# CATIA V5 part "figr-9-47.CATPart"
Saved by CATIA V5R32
Part number: Part1
Bounding box of the stored display mesh (mm): x -229.955 to 192.37, y -118.044 to 79.893, z 0 to 72.429
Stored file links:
  D:\PROJECTS\Project 2022\CATIA V5 6R 2022\Resources\Part Files\c09_catia_v5_6r2022_prt\c09_catia_v5_6r2022_prt\figr-9-47.CATPart
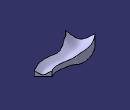
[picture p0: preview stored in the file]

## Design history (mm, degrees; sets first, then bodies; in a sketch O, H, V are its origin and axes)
Body1 (main body)
  Plane1: type Offset, RefPlane yz-plane, Offset 100
  Plane2: type Offset, RefPlane yz-plane, Offset 100, reversed
  Sketch1 on Plane1, origin (100, 0, 0), H (0, 1, 0), V (0, 0, 1)
    point P1 (0, 15.965)
    hyperbola C1
    point P2 (0, 3.0416)
    line L1 (54.8261, 44.8858) -> (54.8261, 0)
    point P5 (54.8261, 0)
    line L2 (-54.8261, 44.8858) -> (-54.8261, 0)
    point P6 (-54.8261, 0)
    line L3 (-54.8261, 0) -> (54.8261, 0)
    coincidence: P1 V, P2 V, P5 H, P6 H
    vertical: L1 V, L2 V
    horizontal: L3 H
  Sketch2 on xy-plane, origin (0, 0, 0), H (1, 0, 0), V (0, 1, 0)
    spline S1 through (-159.6608, -77.1468) (-77.8466, -31.8169) (23.6283, -41.4968) (182.6271, -11.7333)
  Sketch3 on yz-plane, origin (0, 0, 0), H (0, 1, 0), V (0, 0, 1)
    point P1 (0, 18.9787)
    hyperbola C1
    point P2 (0, 2.6681)
    line L1 (48.2237, 37.1764) -> (48.2237, 0)
    point P5 (48.2237, 0)
    line L2 (-43.6563, 34.1546) -> (-43.6563, 0)
    point P6 (-43.6563, 0)
    line L3 (-43.6563, 0) -> (48.2237, 0)
    coincidence: P1 V, P2 V, P5 H, P6 H
    vertical: L1 V, L2 V
    horizontal: L3 H
  Sketch4 on Plane2, origin (-100, 0, 0), H (0, 1, 0), V (0, 0, 1)
    point P1 (0, 140.6052)
    point P2 (0, 41.8972)
    hyperbola C1
    line L1 (78.0478, 72.4293) -> (78.0478, 0)
    point P5 (78.0478, 0)
    line L2 (-78.0478, 72.4293) -> (-78.0478, 0)
    point P6 (-78.0478, 0)
    line L3 (-78.0478, 0) -> (78.0478, 0)
    coincidence: P1 V, P2 V, P5 H, P6 H
    vertical: L1 V, L2 V
    horizontal: L3 H
  Loft1: solid, Sections (Sketch3; Sketch4), Spine Sketch2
